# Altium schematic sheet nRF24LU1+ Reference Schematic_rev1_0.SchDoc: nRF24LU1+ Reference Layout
size A4; DrawnBy: Endre Rindalsholt; Revision: 1.0; SheetNumber: 1; SheetTotal: 1; ProjectNumber: 4359
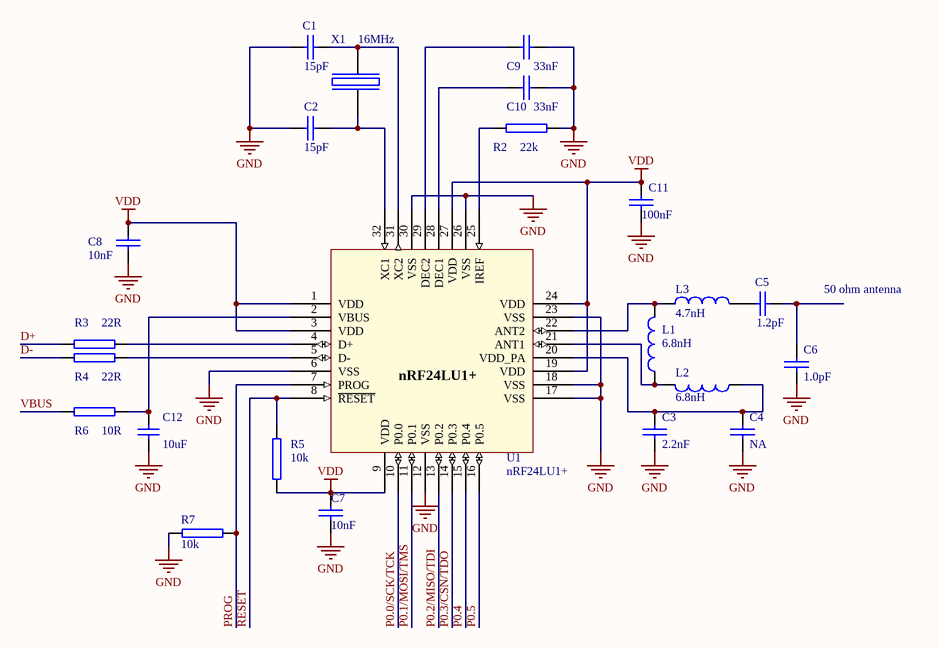
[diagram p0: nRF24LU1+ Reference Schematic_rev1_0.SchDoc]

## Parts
C1  value 15pF  [0402s]  (hidden comment: NPO, +/-2% 50V)
C2  value 15pF  [0402s]  (hidden comment: NPO, +/-2% 50V)
C3  value 2.2nF  [0402s]  (hidden comment: X7R 16V)
C4  value NA  [0402s]  (hidden comment: NP0 50V)
C5  value 1.2pF  [0402s]  (hidden comment: NP0 +/-0.1pF, 50V)
C6  value 1.0pF  [0402s]  (hidden comment: NP0 +/-0.1pF, 50V)
C7  value 10nF  [0402s]  (hidden comment: X7R, +/-10% 50V)
C8  value 10nF  [0402s]  (hidden comment: X7R, +/-10% 50V)
C9  value 33nF  [0402s]  (hidden comment: X7R, +/-10% 50V)
C10  value 33nF  [0402s]  (hidden comment: X7R, +/-10% 50V)
C11  value 100nF  [0402s]  (hidden comment: X7R, +/-10% 50V)
C12  value 10uF  [0805]  (hidden comment: X5R +/-10%, 6.3v)
L1  value 6.8nH  [0402s]  (hidden comment: Murata LQP15MN6N8B02D)
L2  value 6.8nH  [0402s]  (hidden comment: Murata LQP15MN6N8B02D)
L3  value 4.7nH  [0402s]  (hidden comment: Murata LQP15MN4N7B02D)
R2  value 22k  [0402s]  (hidden comment: 1%)
R3  value 22R  [0402s]  (hidden comment: 5%)
R4  value 22R  [0402s]  (hidden comment: 5%)
R5  value 10k  [0402s]  (hidden comment: 5%)
R6  value 10R  [0402s]  (hidden comment: 5%)
R7  value 10k  [0402s]  (hidden comment: 5%)
U1  nRF24LU1+  [QFN32L/5x5]
X1  value 16MHz  [bt-xtal 3225]  (hidden comment: TSX-3225, 16MHz, Cl=9pF, +/-10ppm)

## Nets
GND: C1.2 C2.1 C3.1 C4.1 C6.2 C7.2 C8.2 C9.2 C10.2 C11.2 C12.2 R2.1 R7.1 U1.6(VSS) U1.12(VSS) U1.17(VSS) U1.18(VSS) U1.23(VSS) U1.26(VSS) U1.30(VSS) X1.2(GND) X1.4(GND)
VDD: C7.1 C8.1 C11.1 R5.2 U1.1(VDD) U1.3(VDD) U1.9(VDD) U1.19(VDD) U1.24(VDD) U1.27(VDD)
D+: R3.2
D-: R4.2
P0.0/SCK/TCK: U1.10(P0.0)
P0.1/MOSI/TMS: U1.11(P0.1)
P0.2/MISO/TDI: U1.13(P0.2)
P0.3/CSN/TDO: U1.14(P0.3)
P0.4: U1.15(P0.4)
P0.5: U1.16(P0.5)
PROG: R7.2 U1.7(PROG)
RESET: R5.1 U1.8(~{RESET})
VBUS: R6.2
NetC1_1: C1.1 U1.31(XC2) X1.3(out)
NetC2_2: C2.2 U1.32(XC1) X1.1(inp)
NetC3_2: C3.2 C4.2 L2.1 U1.20(VDD_PA)
NetC5_1: C5.1 C6.1
NetC5_2: C5.2 L3.2
NetC9_1: C9.1 U1.29(DEC2)
NetC10_1: C10.1 U1.28(DEC1)
NetC12_1: C12.1 R6.1 U1.2(VBUS)
NetL1_1: L1.1 L2.2 U1.21(ANT1)
NetL1_2: L1.2 L3.1 U1.22(ANT2)
NetR2_2: R2.2 U1.25(IREF)
NetR3_1: R3.1 U1.4(D+)
NetR4_1: R4.1 U1.5(D-)

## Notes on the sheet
- 50 ohm antenna

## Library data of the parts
C1 C2 C7-C11 = CAP: Capacitor; Part Field 1: 0402
C3-C6 = Cap: Capacitor; Part Field 1: 0402
C12 = Cap: Capacitor
L1-L3 = Inductor: Code_IEC: 1005
R2 R4 = RES2: Resistor; Part Field 1: 1608[0603]
R3 = RES2: Resistor; Part Field 1: 0603s
R5 R7 = RES2: Resistor; Part Field 1: 0402
R6 = RES2: Part Field 1: 0402
U1 = nRF24LU1P: 2.4GHz Transceiver with USB
X1 = BT-XTAL: Crystal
